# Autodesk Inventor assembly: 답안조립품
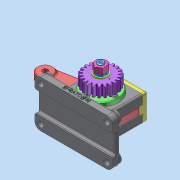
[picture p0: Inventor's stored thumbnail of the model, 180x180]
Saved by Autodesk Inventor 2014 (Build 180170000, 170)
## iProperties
Created: 2026-03
Part Number: 답안조립품
Document SubType Name: Assembly
Designer: dg
Mass: 1676.99 g
Surface Area: 1011.01 cm^2
Volume: 333.535 cm^3
Density: 5.02792 g/cm^3
Author: dg
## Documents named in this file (15)
- C:\Users\dg\Desktop\660303V1002\답안조립품.iam
- C:\Users\dg\Desktop\660303V1002\가져온 구성요소\본체\본체.ipt
- C:\Users\dg\Desktop\660303V1002\가져온 구성요소\플랜지 오일레스 부시\플랜지 오일레스 부시.ipt
- C:\Users\dg\Desktop\660303V1002\가져온 구성요소\앞커버\앞커버.ipt
- C:\Users\dg\Desktop\660303V1002\가져온 구성요소\6각 구멍붙이 볼트 M4x10\6각 구멍붙이 볼트 M4x10.ipt
- C:\Users\dg\Desktop\660303V1002\가져온 구성요소\편심축\편심축.ipt
- C:\Users\dg\Desktop\660303V1002\가져온 구성요소\평행키 4x4x10\평행키 4x4x10.ipt
- C:\Users\dg\Desktop\660303V1002\가져온 구성요소\스퍼기어\스퍼기어.ipt
- C:\Users\dg\Desktop\660303V1002\가져온 구성요소\6각 너트 M10\6각 너트 M10.ipt
- C:\Users\dg\Desktop\660303V1002\가져온 구성요소\스프링와셔 M10\스프링와셔 M10.ipt
- C:\Users\dg\Desktop\660303V1002\가져온 구성요소\평와셔 M10\평와셔 M10.ipt
- C:\Users\dg\Desktop\660303V1002\가져온 구성요소\로드\로드.ipt
- C:\Users\dg\Desktop\660303V1002\가져온 구성요소\윗커버\윗커버.ipt
- C:\Users\dg\Desktop\660303V1002\가져온 구성요소\그리스 니플 M6x0.75\그리스 니플 M6x0.75.ipt
- C:\Users\dg\Desktop\660303V1002\가져온 구성요소\실링\실링.ipt
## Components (12 placed, 4 different names)
1. 플랜지 오일레스 부시:1
2. 플랜지 오일레스 부시:2
3. 6각 구멍붙이 볼트 M4x10:1
4. 6각 구멍붙이 볼트 M4x10:2
5. 6각 구멍붙이 볼트 M4x10:3
6. 6각 구멍붙이 볼트 M4x10:4
7. 6각 너트 M10:1
8. 6각 구멍붙이 볼트 M4x10:5
9. 6각 구멍붙이 볼트 M4x10:6
10. 6각 구멍붙이 볼트 M4x10:7
11. 6각 구멍붙이 볼트 M4x10:8
12. 그리스 니플 M6x0.75:1
